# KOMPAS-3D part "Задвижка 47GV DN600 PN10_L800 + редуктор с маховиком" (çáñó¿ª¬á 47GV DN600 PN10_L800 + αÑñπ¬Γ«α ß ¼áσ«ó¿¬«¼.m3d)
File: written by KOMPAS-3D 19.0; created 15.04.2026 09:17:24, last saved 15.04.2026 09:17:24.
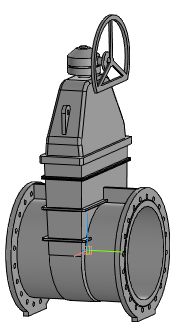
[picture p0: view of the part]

Document properties: Автор: Энергия; Полное имя файла: ..\..\Задвижка 47GV DN600 PN10_L800 + редуктор с маховиком.a3d

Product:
- Part/product: Задвижка 47GV DN600 PN10_L800 + редуктор с маховиком
    Масса: 1682.34

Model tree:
1. Операция без истории:1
